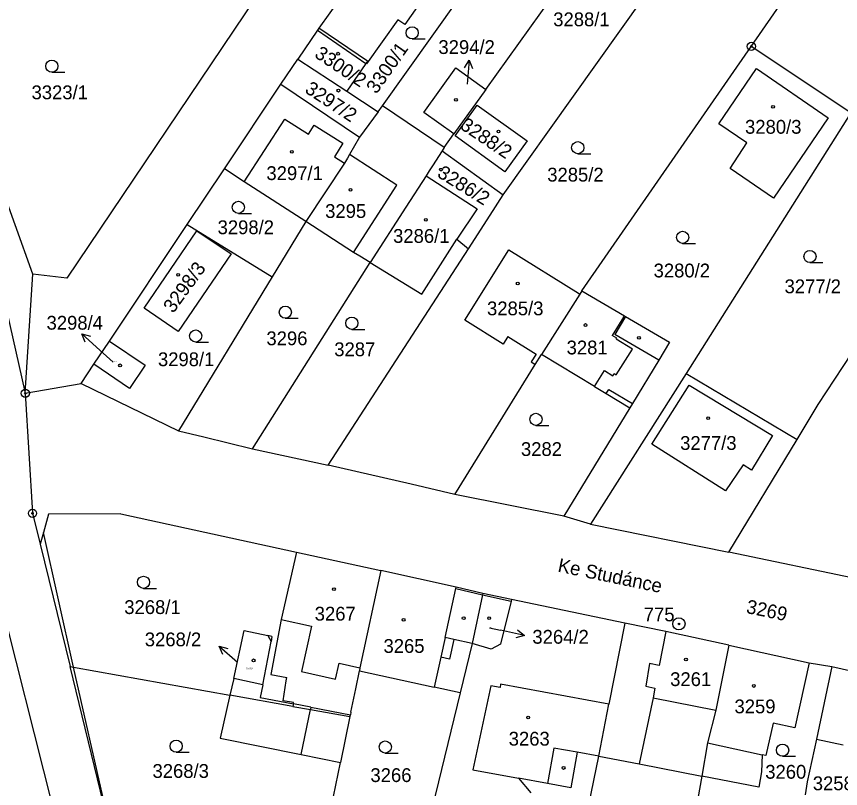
# Model space of a CAD drawing. Extents: x -755819 to -753140, y -1169796 to -1166000.
# Drawn here: x -754380.1 to -754278.6, y -1168994.1 to -1168898.9 of the extents above; entities that cross this region are included whole.
import ezdxf

# ---------------------------------------------------------------- set-up
doc = ezdxf.new("R2010")
doc.units = 0
for name, color, linetype in [('Vrstva 1', 7, 'Continuous'), ('Vrstva 10', 7, 'Continuous'), ('Vrstva 15', 7, 'Continuous'), ('Vrstva 16', 7, 'Continuous'), ('Vrstva 17', 7, 'Continuous'), ('Vrstva 18', 7, 'Continuous'), ('Vrstva 19', 7, 'Continuous'), ('Vrstva 24', 7, 'Continuous'), ('Vrstva 25', 7, 'Continuous'), ('Vrstva 4', 7, 'Continuous'), ('Vrstva 6', 7, 'Continuous')]:
    doc.layers.add(name, color=color, linetype=linetype)

msp = doc.modelspace()

# ---------------------------------------------------------------- linework, layer by layer
at = {"layer": 'Vrstva 1'}
for p, q in [((-754396.56, -1168868.29), (-754379.05, -1168945.33)), ((-754322.29, -1168907.88), (-754296.73, -1168872.18)), ((-754320.17, -1168920.89), (-754296.55, -1168887.75)), ((-754347.46, -1168891.84), (-754373.92, -1168931.14)), ((-754337.33, -1168892.56), (-754342.88, -1168900.34)), ((-754289.57, -1168902.57), (-754284.78, -1168895.66)), ((-754335.01, -1168909.89), (-754325.74, -1168896.85)), ((-754330.71, -1168897.67), (-754332.28, -1168899.89)), ((-754333.13, -1168899.29), (-754337, -1168904.73)), ((-754332.28, -1168899.89), (-754333.13, -1168899.29)), ((-754343.03, -1168900.56), (-754345.45, -1168904.13)), ((-754342.88, -1168900.34), (-754343.03, -1168900.56)), ((-754336.88, -1168904.4), (-754342.88, -1168900.34)), ((-754310.45, -1168932.7), (-754289.57, -1168902.57)), ((-754277.3, -1168910.77), (-754289.57, -1168902.57)), ((-754347.54, -1168907.23), (-754345.45, -1168904.13)), ((-754345.45, -1168904.13), (-754339.41, -1168908.11)), ((-754337.07, -1168904.68), (-754339.41, -1168908.11)), ((-754336.88, -1168904.4), (-754337.07, -1168904.68)), ((-754337, -1168904.73), (-754337.07, -1168904.68)), ((-754329.94, -1168910.72), (-754326, -1168905.23)), ((-754326, -1168905.23), (-754322.29, -1168907.88)), ((-754293.55, -1168912.13), (-754288.93, -1168905.28)), ((-754288.93, -1168905.28), (-754280.08, -1168911.36)), ((-754354.49, -1168917.65), (-754347.54, -1168907.23)), ((-754347.54, -1168907.23), (-754337.87, -1168913.75)), ((-754322.29, -1168907.88), (-754326.22, -1168913.37)), ((-754339.41, -1168908.11), (-754335.55, -1168910.65)), ((-754335.55, -1168910.65), (-754335.01, -1168909.89)), ((-754327.41, -1168915.03), (-754335.01, -1168909.89)), ((-754326.07, -1168913.59), (-754323.36, -1168909.8)), ((-754323.36, -1168909.8), (-754317.2, -1168914.22)), ((-754335.55, -1168910.65), (-754337.87, -1168913.75)), ((-754326.22, -1168913.37), (-754329.94, -1168910.72)), ((-754277.3, -1168910.77), (-754297.61, -1168942.88)), ((-754280.08, -1168911.36), (-754286.82, -1168921.27)), ((-754290.11, -1168914.48), (-754293.55, -1168912.13)), ((-754337.87, -1168913.75), (-754339.09, -1168915.92)), ((-754327.41, -1168915.03), (-754326.22, -1168913.37)), ((-754319.93, -1168918.02), (-754326.07, -1168913.59)), ((-754327.41, -1168915.03), (-754327.69, -1168915.45)), ((-754317.2, -1168914.22), (-754319.93, -1168918.02)), ((-754292.18, -1168917.61), (-754290.11, -1168914.48)), ((-754339.09, -1168915.92), (-754339.34, -1168916.37)), ((-754327.69, -1168915.45), (-754328.88, -1168917.3)), ((-754327.69, -1168915.45), (-754320.17, -1168920.89)), ((-754339.72, -1168916.96), (-754344.47, -1168924.17)), ((-754339.34, -1168916.37), (-754339.72, -1168916.96)), ((-754378.13, -1168930.64), (-754382.87, -1168917.47)), ((-754359.09, -1168924.53), (-754354.49, -1168917.65)), ((-754352.09, -1168919.27), (-754354.49, -1168917.65)), ((-754329.28, -1168917.93), (-754329.66, -1168918.53)), ((-754328.88, -1168917.3), (-754329.28, -1168917.93)), ((-754286.82, -1168921.27), (-754292.18, -1168917.61)), ((-754329.66, -1168918.53), (-754332.16, -1168922.4)), ((-754329.66, -1168918.53), (-754323.37, -1168922.61)), ((-754344.47, -1168924.17), (-754352.09, -1168919.27)), ((-754321.75, -1168923.36), (-754320.17, -1168920.89)), ((-754332.16, -1168922.4), (-754336.53, -1168929.23)), ((-754323.37, -1168922.61), (-754325.86, -1168926.35)), ((-754344.47, -1168924.17), (-754348.61, -1168930.98)), ((-754338.58, -1168927.96), (-754344.47, -1168924.17)), ((-754324.43, -1168927.54), (-754321.75, -1168923.36)), ((-754368.68, -1168938.89), (-754359.09, -1168924.53)), ((-754359.09, -1168924.53), (-754348.61, -1168930.98)), ((-754364.41, -1168934.84), (-754357.89, -1168925.29)), ((-754357.89, -1168925.29), (-754353.69, -1168928.15)), ((-754330.19, -1168933.13), (-754325.86, -1168926.35)), ((-754325.86, -1168926.35), (-754324.43, -1168927.54)), ((-754353.69, -1168928.15), (-754360.19, -1168937.71)), ((-754341.72, -1168954.18), (-754324.43, -1168927.54)), ((-754337.83, -1168928.44), (-754338.58, -1168927.96)), ((-754324.89, -1168936.34), (-754319.45, -1168927.64)), ((-754319.45, -1168927.64), (-754310.88, -1168933)), ((-754351.06, -1168952.16), (-754336.53, -1168929.23)), ((-754336.53, -1168929.23), (-754337.83, -1168928.44)), ((-754336.53, -1168929.23), (-754330.19, -1168933.13)), ((-754379.05, -1168945.33), (-754378.13, -1168930.64)), ((-754373.92, -1168931.14), (-754378.13, -1168930.64)), ((-754348.61, -1168930.98), (-754360.17, -1168949.97)), ((-754310.71, -1168933.11), (-754315.44, -1168940.55)), ((-754310.88, -1168933), (-754310.71, -1168933.11)), ((-754310.45, -1168932.7), (-754310.71, -1168933.11)), ((-754310.45, -1168932.7), (-754305.19, -1168935.79)), ((-754360.19, -1168937.71), (-754364.41, -1168934.84)), ((-754320.17, -1168939.28), (-754324.89, -1168936.34)), ((-754305.19, -1168935.79), (-754305.09, -1168935.85)), ((-754305.09, -1168935.85), (-754299.64, -1168939.05)), ((-754281.33, -1168946.72), (-754275, -1168937.06)), ((-754319.58, -1168938.34), (-754320.17, -1168939.28)), ((-754319.58, -1168938.34), (-754316.1, -1168940.51)), ((-754370.59, -1168941.76), (-754368.68, -1168938.89)), ((-754368.68, -1168938.89), (-754364.27, -1168941.87)), ((-754299.64, -1168939.05), (-754300.98, -1168941.26)), ((-754316.1, -1168940.51), (-754316.69, -1168941.46)), ((-754316.69, -1168941.46), (-754316.37, -1168941.65)), ((-754316.19, -1168941.77), (-754315.44, -1168940.55)), ((-754308.9, -1168944.5), (-754315.44, -1168940.55)), ((-754300.98, -1168941.26), (-754304.22, -1168946.59)), ((-754372.18, -1168944.13), (-754370.59, -1168941.76)), ((-754366.21, -1168944.75), (-754370.59, -1168941.76)), ((-754364.27, -1168941.87), (-754366.21, -1168944.75)), ((-754326.09, -1168957.79), (-754316.19, -1168941.77)), ((-754316.37, -1168941.65), (-754316.19, -1168941.77)), ((-754297.61, -1168942.88), (-754309.38, -1168961.47)), ((-754297.61, -1168942.88), (-754283.93, -1168951.01)), ((-754379.05, -1168945.33), (-754372.18, -1168944.13)), ((-754372.18, -1168944.13), (-754360.17, -1168949.97)), ((-754308.9, -1168944.5), (-754307.47, -1168945.37)), ((-754379.05, -1168945.33), (-754378.16, -1168960.13)), ((-754307.47, -1168945.37), (-754304.55, -1168947.13)), ((-754304.55, -1168947.13), (-754312.67, -1168960.49)), ((-754304.22, -1168946.59), (-754304.55, -1168947.13)), ((-754283.93, -1168951.01), (-754281.33, -1168946.72)), ((-754360.17, -1168949.97), (-754357.06, -1168950.72)), ((-754357.06, -1168950.72), (-754351.06, -1168952.16)), ((-754292.32, -1168964.93), (-754283.93, -1168951.01)), ((-754351.06, -1168952.16), (-754341.72, -1168954.18)), ((-754331.48, -1168956.55), (-754341.72, -1168954.18)), ((-754326.09, -1168957.79), (-754331.48, -1168956.55)), ((-754312.67, -1168960.49), (-754326.09, -1168957.79)), ((-754378.16, -1168960.13), (-754377.23, -1168963.95)), ((-754376.2, -1168960.23), (-754376.82, -1168962.5)), ((-754367.27, -1168960.2), (-754376.2, -1168960.23)), ((-754367.27, -1168960.2), (-754345.64, -1168964.92)), ((-754309.38, -1168961.47), (-754312.67, -1168960.49)), ((-754309.38, -1168961.47), (-754292.32, -1168964.93)), ((-754376.82, -1168962.5), (-754377.23, -1168963.95)), ((-754377.23, -1168963.95), (-754373.54, -1168979.01)), ((-754345.64, -1168964.92), (-754347.5, -1168973.21)), ((-754345.64, -1168964.92), (-754335.23, -1168967.19)), ((-754262.87, -1168971.05), (-754292.32, -1168964.93)), ((-754335.23, -1168967.19), (-754337.82, -1168979.18)), ((-754325.95, -1168969.24), (-754335.23, -1168967.19)), ((-754322.66, -1168970.03), (-754325.95, -1168969.24)), ((-754322.69, -1168970.17), (-754323.97, -1168976.18)), ((-754322.66, -1168970.03), (-754322.69, -1168970.17)), ((-754319.13, -1168970.76), (-754322.66, -1168970.03)), ((-754319.13, -1168970.76), (-754319.17, -1168970.96)), ((-754305.15, -1168973.66), (-754319.13, -1168970.76)), ((-754319.17, -1168970.96), (-754320.49, -1168976.26)), ((-754347.5, -1168973.21), (-754348.8, -1168980)), ((-754305.15, -1168973.66), (-754307.14, -1168983.64)), ((-754300.12, -1168974.69), (-754305.15, -1168973.66)), ((-754353.36, -1168980.47), (-754352.07, -1168974.56)), ((-754352.07, -1168974.56), (-754349.14, -1168975.2)), ((-754300.12, -1168974.69), (-754300.91, -1168978.87)), ((-754292.35, -1168976.39), (-754300.12, -1168974.69)), ((-754349.78, -1168981.25), (-754348.76, -1168975.91)), ((-754348.65, -1168975.31), (-754349.14, -1168975.2)), ((-754348.65, -1168975.31), (-754348.76, -1168975.91)), ((-754323.97, -1168976.18), (-754325.46, -1168982.26)), ((-754321.62, -1168976.87), (-754323.97, -1168976.18)), ((-754320.49, -1168976.26), (-754321.62, -1168976.87)), ((-754292.35, -1168976.39), (-754293.94, -1168984.4)), ((-754292.35, -1168976.39), (-754282.45, -1168978.56)), ((-754369.4, -1168995.91), (-754373.54, -1168979.01)), ((-754302.12, -1168978.64), (-754302.57, -1168981.44)), ((-754300.91, -1168978.87), (-754302.12, -1168978.64)), ((-754282.45, -1168978.56), (-754284.2, -1168986.58)), ((-754282.45, -1168978.56), (-754279.66, -1168979.01)), ((-754279.66, -1168979.01), (-754281.52, -1168987.95)), ((-754279.66, -1168979.01), (-754268.54, -1168981.47)), ((-754348.8, -1168980), (-754346.82, -1168980.37)), ((-754338.32, -1168981.76), (-754337.86, -1168979.53)), ((-754337.82, -1168979.18), (-754337.86, -1168979.53)), ((-754337.86, -1168979.53), (-754328.65, -1168981.56)), ((-754349.78, -1168981.25), (-754353.36, -1168980.47)), ((-754347.26, -1168983.23), (-754346.88, -1168980.76)), ((-754346.88, -1168980.76), (-754346.82, -1168980.37)), ((-754338.91, -1168984.63), (-754338.32, -1168981.76)), ((-754325.46, -1168982.26), (-754328.65, -1168981.56)), ((-754321.66, -1168981.38), (-754323.88, -1168991.76)), ((-754320.54, -1168981.59), (-754321.66, -1168981.38)), ((-754320.46, -1168981.2), (-754320.54, -1168981.59)), ((-754307.14, -1168983.64), (-754320.46, -1168981.2)), ((-754302.57, -1168981.44), (-754301.44, -1168981.66)), ((-754301.44, -1168981.66), (-754301.67, -1168982.86)), ((-754325.46, -1168982.26), (-754330.56, -1169003.14)), ((-754301.67, -1168982.86), (-754303.38, -1168991.01)), ((-754345.98, -1168983.45), (-754347.26, -1168983.23)), ((-754346.01, -1168983.62), (-754346.07, -1168983.93)), ((-754346.01, -1168983.62), (-754345.98, -1168983.45)), ((-754308.36, -1168990.05), (-754307.14, -1168983.64)), ((-754339.03, -1168985.19), (-754338.98, -1168984.96)), ((-754338.91, -1168984.63), (-754338.98, -1168984.96)), ((-754293.94, -1168984.4), (-754294.98, -1168988.42)), ((-754339.03, -1168985.19), (-754340.19, -1168990.83)), ((-754286.89, -1168985.99), (-754287.77, -1168990)), ((-754284.2, -1168986.58), (-754286.89, -1168985.99)), ((-754281.52, -1168987.95), (-754282.68, -1168993.23)), ((-754294.98, -1168988.42), (-754295.65, -1168992.51)), ((-754309.6, -1168996.07), (-754308.36, -1168990.05)), ((-754288.22, -1168989.9), (-754288.3, -1168992.01)), ((-754287.77, -1168990), (-754288.22, -1168989.9)), ((-754342.29, -1169000.96), (-754340.19, -1168990.83)), ((-754303.38, -1168991.01), (-754295.65, -1168992.51)), ((-754323.88, -1168991.76), (-754318.27, -1168992.78)), ((-754288.3, -1168992.01), (-754288.63, -1168993.87)), ((-754318.27, -1168992.78), (-754316.73, -1168994.57)), ((-754295.65, -1168992.51), (-754296.55, -1168997.5)), ((-754288.63, -1168993.87), (-754295.65, -1168992.51)), ((-754282.68, -1168993.23), (-754282.93, -1168994.82))]:
    msp.add_line(p, q, dxfattribs=at)
at = {"layer": 'Vrstva 10'}
msp.add_line((-754346.69, -1169111.14), (-754392.72, -1168928.69), dxfattribs=at)
at = {"layer": 'Vrstva 16'}
for p, q in [((-754324.35, -1168904.26), (-754324.58, -1168907.25)), ((-754372.08, -1168937.99), (-754369.86, -1168940.01)), ((-754368.24, -1168941.48), (-754369.86, -1168940.01)), ((-754321.83, -1168974.24), (-754320.46, -1168974.54)), ((-754317.53, -1168975.18), (-754320.46, -1168974.54)), ((-754355.15, -1168976.52), (-754352.89, -1168978.49))]:
    msp.add_line(p, q, dxfattribs=at)
for points in [[(-754324.92, -1168905.22), (-754324.35, -1168904.26), (-754323.93, -1168905.29)], [(-754371.68, -1168939.03), (-754372.08, -1168937.99), (-754371, -1168938.29)], [(-754318.4, -1168974.48), (-754317.53, -1168975.18), (-754318.61, -1168975.46)], [(-754354.72, -1168977.55), (-754355.15, -1168976.52), (-754354.07, -1168976.8)]]:
    msp.add_lwpolyline(points, dxfattribs=at)
at = {"layer": 'Vrstva 24'}
for centre, radius in [((-754289.57, -1168902.57), 0.5), ((-754289.57, -1168902.57), 0.1), ((-754379.05, -1168945.33), 0.5), ((-754379.05, -1168945.33), 0.1), ((-754378.16, -1168960.13), 0.5), ((-754378.16, -1168960.13), 0.1), ((-754298.49, -1168973.76), 0.75), ((-754298.49, -1168973.76), 0.1)]:
    msp.add_circle(centre, radius, dxfattribs=at)
at = {"layer": 'Vrstva 25'}
for p, q in [((-754331.37, -1168901.65), (-754329.77, -1168901.65)), ((-754375.78, -1168905.77), (-754374.18, -1168905.77)), ((-754310.96, -1168915.81), (-754309.36, -1168915.81)), ((-754352.79, -1168923.16), (-754351.19, -1168923.16)), ((-754298.03, -1168926.86), (-754296.43, -1168926.86)), ((-754282.34, -1168929.23), (-754280.74, -1168929.23)), ((-754347, -1168936.09), (-754345.4, -1168936.09)), ((-754338.8, -1168937.45), (-754337.2, -1168937.45)), ((-754358.05, -1168939.02), (-754356.45, -1168939.02)), ((-754316.11, -1168949.29), (-754314.51, -1168949.29)), ((-754364.48, -1168969.38), (-754362.88, -1168969.38)), ((-754360.45, -1168989.57), (-754358.85, -1168989.57)), ((-754334.68, -1168989.68), (-754333.08, -1168989.68)), ((-754285.71, -1168990.07), (-754284.11, -1168990.07))]:
    msp.add_line(p, q, dxfattribs=at)
msp.add_lwpolyline([(-754327.72, -1168917.61), (-754327.63, -1168917.76), (-754327.72, -1168917.91), (-754327.9, -1168917.91), (-754327.99, -1168917.76), (-754327.9, -1168917.61)], close=True, dxfattribs=at)
for centre, radius in [((-754331.37, -1168900.9), 0.75), ((-754340.5, -1168903.48), 0.175), ((-754375.78, -1168905.02), 0.75), ((-754340.46, -1168908.03), 0.175), ((-754325.97, -1168909.17), 0.175), ((-754286.89, -1168910.02), 0.175), ((-754320.72, -1168913.07), 0.175), ((-754310.96, -1168915.06), 0.75), ((-754346.19, -1168915.58), 0.175), ((-754338.96, -1168920.25), 0.175), ((-754352.79, -1168922.41), 0.75), ((-754329.68, -1168923.96), 0.175), ((-754298.03, -1168926.11), 0.75), ((-754282.34, -1168928.48), 0.75), ((-754360.21, -1168930.73), 0.175), ((-754318.36, -1168931.8), 0.175), ((-754347, -1168935.34), 0.75), ((-754338.8, -1168936.7), 0.75), ((-754310, -1168936.92), 0.175), ((-754358.05, -1168938.27), 0.75), ((-754303.42, -1168938.5), 0.175), ((-754367.37, -1168941.89), 0.175), ((-754316.11, -1168948.54), 0.75), ((-754294.88, -1168948.39), 0.175), ((-754364.48, -1168968.63), 0.75), ((-754341.01, -1168969.48), 0.175), ((-754325.02, -1168973.05), 0.175), ((-754321.87, -1168973.05), 0.175), ((-754332.42, -1168973.25), 0.175), ((-754297.62, -1168978.15), 0.175), ((-754350.91, -1168978.25), 0.175), ((-754289.25, -1168981.41), 0.175), ((-754317.08, -1168985.29), 0.175), ((-754360.45, -1168988.82), 0.75), ((-754334.68, -1168988.93), 0.75), ((-754285.71, -1168989.32), 0.75), ((-754312.7, -1168991.52), 0.175)]:
    msp.add_circle(centre, radius, dxfattribs=at)
at = {"layer": 'Vrstva 4'}
for p, q in [((-754343.03, -1168900.56), (-754337.07, -1168904.68)), ((-754352.09, -1168919.27), (-754347.05, -1168911.55)), ((-754347.05, -1168911.55), (-754344.13, -1168913.38)), ((-754344.13, -1168913.38), (-754343.45, -1168912.29)), ((-754343.45, -1168912.29), (-754339.9, -1168914.51)), ((-754339.9, -1168914.51), (-754340.95, -1168916.19)), ((-754333.25, -1168919.67), (-754339.09, -1168915.92)), ((-754340.95, -1168916.19), (-754339.72, -1168916.96)), ((-754338.58, -1168927.96), (-754333.25, -1168919.67)), ((-754305.31, -1168935.97), (-754306.72, -1168938.19)), ((-754305.09, -1168935.85), (-754306.4, -1168938.08)), ((-754305.31, -1168935.97), (-754305.19, -1168935.79)), ((-754306.13, -1168938.55), (-754306.72, -1168938.19)), ((-754300.98, -1168941.26), (-754306.4, -1168938.08)), ((-754306.21, -1168938.67), (-754306.13, -1168938.55)), ((-754304.22, -1168939.9), (-754306.21, -1168938.67)), ((-754306.22, -1168943.04), (-754304.22, -1168939.9)), ((-754308.9, -1168944.5), (-754307.66, -1168942.54)), ((-754307.66, -1168942.54), (-754306.65, -1168943.18)), ((-754306.65, -1168943.18), (-754306.46, -1168942.89)), ((-754306.46, -1168942.89), (-754306.22, -1168943.04)), ((-754301.83, -1168951.59), (-754297.22, -1168944.33)), ((-754297.22, -1168944.33), (-754286.97, -1168950.52)), ((-754307.47, -1168945.37), (-754307.12, -1168944.86)), ((-754307.12, -1168944.86), (-754304.22, -1168946.59)), ((-754286.97, -1168950.52), (-754289.55, -1168954.8)), ((-754292.75, -1168957.36), (-754301.83, -1168951.59)), ((-754290.59, -1168954.17), (-754292.75, -1168957.36)), ((-754289.55, -1168954.8), (-754290.59, -1168954.17)), ((-754373.09, -1168979.09), (-754376.82, -1168962.5)), ((-754327.31, -1168975.45), (-754325.98, -1168969.38)), ((-754325.98, -1168969.38), (-754325.95, -1168969.24)), ((-754325.98, -1168969.38), (-754322.69, -1168970.17)), ((-754322.69, -1168970.17), (-754319.17, -1168970.96)), ((-754347.5, -1168973.21), (-754343.76, -1168974.05)), ((-754343.76, -1168974.05), (-754345.01, -1168979.62)), ((-754349.14, -1168975.2), (-754348.76, -1168975.91)), ((-754327.31, -1168975.45), (-754327.84, -1168977.87)), ((-754326.24, -1168975.68), (-754327.31, -1168975.45)), ((-754326.24, -1168975.68), (-754326.77, -1168978.11)), ((-754323.97, -1168976.18), (-754326.24, -1168975.68)), ((-754327.84, -1168977.87), (-754328.65, -1168981.56)), ((-754326.77, -1168978.11), (-754327.84, -1168977.87)), ((-754340.82, -1168980.56), (-754340.38, -1168978.61)), ((-754340.38, -1168978.61), (-754337.82, -1168979.18)), ((-754369.3, -1168995.93), (-754373.09, -1168979.09)), ((-754345.01, -1168979.62), (-754340.82, -1168980.56)), ((-754353.36, -1168980.47), (-754353.83, -1168982.54)), ((-754349.78, -1168981.25), (-754350.09, -1168982.83)), ((-754353.83, -1168982.54), (-754355.02, -1168987.85)), ((-754350.09, -1168982.83), (-754346.01, -1168983.62)), ((-754301.67, -1168982.86), (-754293.94, -1168984.4)), ((-754343.84, -1168984.04), (-754346.01, -1168983.62)), ((-754343.84, -1168984.04), (-754343.9, -1168984.32)), ((-754343.84, -1168984.04), (-754338.98, -1168984.96)), ((-754345.04, -1168989.86), (-754343.9, -1168984.32)), ((-754355.02, -1168987.85), (-754345.04, -1168989.86)), ((-754281.52, -1168987.95), (-754278.25, -1168988.65)), ((-754313.9, -1168989.06), (-754314.69, -1168993.43)), ((-754311.03, -1168989.57), (-754313.9, -1168989.06)), ((-754294.98, -1168988.42), (-754288.22, -1168989.9)), ((-754345.04, -1168989.86), (-754340.19, -1168990.83)), ((-754311.03, -1168989.57), (-754311.82, -1168993.95)), ((-754308.36, -1168990.05), (-754311.03, -1168989.57)), ((-754308.36, -1168990.05), (-754303.38, -1168991.01)), ((-754314.69, -1168993.43), (-754318.27, -1168992.78)), ((-754311.82, -1168993.95), (-754314.69, -1168993.43))]:
    msp.add_line(p, q, dxfattribs=at)
at = {"layer": 'Vrstva 6'}
for p, q in [((-754373.54, -1168979.01), (-754373.09, -1168979.09)), ((-754373.09, -1168979.09), (-754353.83, -1168982.54)), ((-754346.07, -1168983.93), (-754353.83, -1168982.54)), ((-754346.07, -1168983.93), (-754343.9, -1168984.32)), ((-754343.9, -1168984.32), (-754339.03, -1168985.19))]:
    msp.add_line(p, q, dxfattribs=at)

# ---------------------------------------------------------------- texts
at = {"layer": 'Vrstva 15'}
msp.add_text('Ke Studánce', height=1.7, rotation=348.301, dxfattribs=at).set_placement((-754313.51, -1168967.31))
at = {"layer": 'Vrstva 16'}
for s, p in [('3294/2', (-754328.13, -1168903.51)), ('3298/4', (-754376.43, -1168937.49)), ('3268/2', (-754364.32, -1168976.52)), ('3264/2', (-754316.55, -1168976.2)), ('3258/3', (-754281.99, -1168994.26))]:
    msp.add_text(s, height=1.7, dxfattribs=at).set_placement(p)
at = {"layer": 'Vrstva 17'}
msp.add_text('775', height=1.7, dxfattribs=at).set_placement((-754302.82, -1168973.44))
at = {"layer": 'Vrstva 18'}
for s, p in [('3288/1', (-754313.98, -1168900.09)), ('3323/1', (-754378.28, -1168909.09)), ('3285/2', (-754314.72, -1168919.23)), ('3298/2', (-754355.35, -1168925.72)), ('3280/2', (-754301.61, -1168931.05)), ('3277/2', (-754285.47, -1168933)), ('3296', (-754349.33, -1168939.41)), ('3287', (-754340.97, -1168940.76)), ('3298/1', (-754362.7, -1168941.99)), ('3282', (-754317.96, -1168953.06)), ('3268/1', (-754366.85, -1168972.54)), ('3268/3', (-754363.37, -1168992.74)), ('3260', (-754287.85, -1168992.84)), ('3266', (-754336.51, -1168993.25))]:
    msp.add_text(s, height=1.7, dxfattribs=at).set_placement(p)
for s, rotation, p in [('3300/1', 54.8894, (-754335.77, -1168908.53)), ('3269', 348.301, (-754290.29, -1168972.4))]:
    msp.add_text(s, height=1.7, rotation=rotation, dxfattribs=at).set_placement(p)
at = {"layer": 'Vrstva 19'}
for s, rotation, p in [('3300/2', 326.2422, (-754343.52, -1168903.82)), ('3297/2', 326.7005, (-754344.71, -1168908.17)), ('3288/2', 326.1849, (-754325.58, -1168912.64)), ('3286/2', 328.1329, (-754328.4, -1168918.57)), ('3298/3', 53.9726, (-754360.81, -1168935.55))]:
    msp.add_text(s, height=1.7, rotation=rotation, dxfattribs=at).set_placement(p)
for s, height, p in [('3294/2', 0.1, (-754324.57, -1168907.25)), ('3280/3', 1.7, (-754290.34, -1168913.34)), ('3297/1', 1.7, (-754349.33, -1168919.05)), ('3295', 1.7, (-754342.09, -1168923.72)), ('3286/1', 1.7, (-754333.72, -1168926.79)), ('3285/3', 1.7, (-754322.14, -1168935.72)), ('3281', 1.7, (-754312.33, -1168940.54)), ('3298/4', 0.1, (-754368.23, -1168941.48)), ('3277/3', 1.7, (-754298.34, -1168952.31)), ('3267', 1.7, (-754343.38, -1168973.35)), ('3264/2', 0.1, (-754321.82, -1168974.24)), ('3265', 1.7, (-754334.9, -1168977.33)), ('3268/2', 0.2, (-754351.85, -1168979.37)), ('3261', 1.7, (-754299.57, -1168981.42)), ('3259', 1.7, (-754291.64, -1168984.78)), ('3263', 1.7, (-754319.47, -1168988.76))]:
    msp.add_text(s, height=height, dxfattribs=at).set_placement(p)

doc.saveas('drawing.dxf')
